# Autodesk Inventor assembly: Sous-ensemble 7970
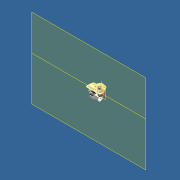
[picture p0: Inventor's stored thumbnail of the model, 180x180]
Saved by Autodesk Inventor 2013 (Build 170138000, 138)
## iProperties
Created: 2011-10
Part Number: Sous-ensemble 7970
Document SubType Name: Assembly
Designer: Laur
Author: Laur
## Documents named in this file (6)
- D:\_an13-14\FORMULAIRE_2014\Sujet E4 Poissy 2014\Modélisation_7970_shimano_2014\Sous-ensemble 7970.iam
- D:\_an13-14\FORMULAIRE_2014\Sujet E4 Poissy 2014\Modélisation_7970_shimano_2014\platine PA-GF inter.ipt
- D:\_an13-14\FORMULAIRE_2014\Sujet E4 Poissy 2014\Modélisation_7970_shimano_2014\cage et arbre-vis sans fin.iam
- D:\_an13-14\FORMULAIRE_2014\Sujet E4 Poissy 2014\Modélisation_7970_shimano_2014\connecteur.ipt
- D:\_an13-14\FORMULAIRE_2014\Sujet E4 Poissy 2014\Modélisation_7970_shimano_2014\contacts connecteur.ipt
- D:\_an13-14\FORMULAIRE_2014\Sujet E4 Poissy 2014\Modélisation_7970_shimano_2014\Butée axiale vis sans fin.ipt
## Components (5 placed, 5 different names)
1. platine PA-GF inter:1 — Angle:1, pos selon axe roue / platine, ENTRAXE roue&vis 10mm, plan de création connecteur, pos2 butée, pos1 butée, pos3 butée, plan de création broches du connecteur, Affleurement:3
2. cage et arbre-vis sans fin:1 [sub-assembly] — Angle:1, pos selon axe roue / platine, ENTRAXE roue&vis 10mm
3. connecteur:1 — plan de création connecteur, Affleurement:3
4. contacts connecteur:1 — plan de création broches du connecteur
5. Butée axiale vis sans fin:1 — pos2 butée, pos1 butée, pos3 butée
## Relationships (9: Mate 5, Flush 3, Angle 1)
- Angle:1: platine PA-GF inter:1 ↔ cage et arbre-vis sans fin:1
- pos selon axe roue / platine [Mate]: platine PA-GF inter:1 ↔ cage et arbre-vis sans fin:1
- ENTRAXE roue&vis 10mm [Mate]: platine PA-GF inter:1 ↔ cage et arbre-vis sans fin:1
- plan de création connecteur [Flush]: platine PA-GF inter:1 ↔ connecteur:1
- plan de création broches du connecteur [Flush]: platine PA-GF inter:1 ↔ contacts connecteur:1
- pos2 butée [Mate]: platine PA-GF inter:1 ↔ Butée axiale vis sans fin:1
- pos1 butée [Mate]: platine PA-GF inter:1 ↔ Butée axiale vis sans fin:1
- pos3 butée [Mate]: platine PA-GF inter:1 ↔ Butée axiale vis sans fin:1
- Affleurement:3 [Flush]: platine PA-GF inter:1 ↔ connecteur:1
